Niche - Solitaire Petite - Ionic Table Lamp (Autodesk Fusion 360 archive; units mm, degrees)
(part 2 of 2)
sketch "Sketch4" plane through (0, 23.8125, 0) normal (0, 1, 0) x axis (-1, 0, 0)
  line L1 (-7.1437, -2.6987) -> (-7.1437, 2.6987)
  line L2 (5.8737, -3.9688) -> (-5.8737, -3.9688)
  line L3 (7.1437, 2.6987) -> (7.1437, -2.6987)
  line L4 (-5.8737, 3.9688) -> (5.8737, 3.9688)
  line L5 (-3.81, 6.604) -> (3.81, 6.604)
  line L6 (3.81, -6.604) -> (-3.81, -6.604)
  line L7 (-10.414, 0) -> (10.414, 0)
  arc A1 centre (-5.8737, 2.6987) radius 1.27 clockwise from (-7.1437, 2.6987) to (-5.8737, 3.9688)
  arc A2 centre (-5.8737, -2.6987) radius 1.27 clockwise from (-5.8737, -3.9688) to (-7.1437, -2.6987)
  arc A3 centre (5.8737, -2.6987) radius 1.27 clockwise from (7.1437, -2.6987) to (5.8737, -3.9688)
  arc A4 centre (5.8737, 2.6987) radius 1.27 clockwise from (5.8737, 3.9688) to (7.1437, 2.6987)
  arc A5 centre (-3.81, 0) radius 6.604 clockwise from (-3.81, -6.604) to (-3.81, 6.604)
  arc A6 centre (3.81, 0) radius 6.604 clockwise from (3.81, 6.604) to (3.81, -6.604)
  point P20 (10.414, 0)
  point P21 (-10.414, 0)
  tangent L5 A5
  tangent A5 L6
  parallel L5 L6
  tangent L6 A6
  tangent L5 A6
  midpoint A6 P20
  midpoint A5 P21
  perpendicular L1 L7
extrude "Extrude4" add sketch "Sketch4" profile of A1 L1 A2 L2 A3 L3 A4 L4 L5 A5 L6 A6 against normal blind 2.286
chamfer "Chamfer2" distance 1.778
fillet "Fillet3" radius 1.778
fillet "Fillet4" radius 0.254
fillet "Fillet5" radius 0.254
fillet "Fillet6" radius 0.254
fillet "Fillet7" radius 3.175
sketch "Sketch5" plane through (0, 0, 0) normal (0, -1, 0) x axis (1, 0, 0)
  line L1 (-13.2397, -5.715) -> (-13.2397, 5.715)
  line L2 (9.6837, -9.271) -> (-9.6837, -9.271)
  line L3 (13.2397, 5.715) -> (13.2397, -5.715)
  line L4 (-9.6837, 9.271) -> (9.6837, 9.271)
  line L5 (-6.35, -3.175) -> (-6.35, 3.175)
  line L6 (6.35, 3.175) -> (-6.35, -3.175)
  line L7 (-6.35, 3.175) -> (6.35, -3.175)
  line L8 (-4.7625, 3.175) -> (-6.35, 3.175)
  line L9 (-4.7625, -3.175) -> (-4.7625, 3.175)
  line L10 (-6.35, -3.175) -> (-4.7625, -3.175)
  line L11 (-6.35, 3.175) -> (-6.35, -3.175)
  line L12 (0, -3.302) -> (0, 3.81)
  line L13 (4.7625, -3.175) -> (4.7625, 3.175)
  line L14 (4.7625, 3.175) -> (6.35, 3.175)
  line L15 (6.35, -3.175) -> (6.35, 3.175)
  line L16 (6.35, -3.175) -> (4.7625, -3.175)
  arc A1 centre (-9.6837, 5.715) radius 3.556 clockwise from (-13.2397, 5.715) to (-9.6837, 9.271)
  arc A2 centre (-9.6837, -5.715) radius 3.556 clockwise from (-9.6837, -9.271) to (-13.2397, -5.715)
  arc A3 centre (9.6837, -5.715) radius 3.556 clockwise from (13.2397, -5.715) to (9.6837, -9.271)
  arc A4 centre (9.6837, 5.715) radius 3.556 clockwise from (9.6837, 9.271) to (13.2397, 5.715)
  point P18 (0, 0)
  point P1 (0, 0)
  point P14 (-6.35, -3.175)
  point P27 (6.35, -3.175)
  point P17 (-6.35, 3.175)
  point P26 (6.35, 3.175)
  point P19 (-4.7625, 3.175)
  point P24 (4.7625, 3.175)
  point P20 (-4.7625, -3.175)
  point P25 (4.7625, -3.175)
  point P21 (-6.35, -3.175)
  point P28 (6.35, -3.175)
  point P15 (6.35, -3.175)
  point P16 (6.35, 3.175)
  coincident L6 P18
  coincident L7 P18
  coincident P1 P18
  horizontal L8
  vertical L9
  horizontal L10
  vertical L11
  vertical L12
  symmetric P14 L12 P27
  symmetric P17 L12 P26
  symmetric P19 L12 P24
  symmetric P20 L12 P25
  symmetric P21 L12 P28
  dimension "d36" distance P15 P16 = 6.35
  dimension "d37" distance P17 P19 = 1.5875
extrude "Extrude5" add sketch "Sketch5" profile of L5 L8 L9 L10 L11 L13 L14 L15 L16 along normal blind 15.875
sketch "Sketch7" plane through (0, 0, 3.175) normal (0, 0, 1) x axis (-1, 0, 0)
  line L1 (-4.7625, 0) -> (-6.35, 0)
  line L2 (-4.7625, 15.875) -> (-4.7625, 0)
  line L3 (-6.35, 15.875) -> (-4.7625, 15.875)
  line L4 (-6.35, 0) -> (-6.35, 15.875)
  line L5 (-4.7625, 15.875) -> (-6.35, 15.875)
  line L6 (-4.7625, 9.525) -> (-4.7625, 15.875)
  line L7 (-6.35, 9.525) -> (-4.7625, 9.525)
  line L8 (-6.35, 15.875) -> (-6.35, 9.525)
  point P5 (-6.35, 15.875)
  point P6 (-6.35, 15.875)
  point P9 (-6.35, 9.525)
  horizontal L5
  vertical L6
  horizontal L7
  vertical L8
  coincident P5 P6
  dimension "d45" distance P6 P9 = 6.35
extrude "Extrude7" add sketch "Sketch7" profile of L2 L3 L4 L5 L6 L7 L8 against normal blind 7.9375 and along normal blind 1.5875
chamfer "Chamfer3" distance 0.508
chamfer "Chamfer4" distance 0.635 distance 0.635
sketch "Sketch6" plane through (6.35, 0, 0) normal (1, 0, 0) x axis (0, 1, 0)
  line L1 (0, -3.175) -> (-9.525, -3.175)
  line L2 (0, 3.175) -> (0, -3.175)
  line L3 (-9.525, 3.175) -> (0, 3.175)
  line L4 (-15.367, -4.6355) -> (-15.367, 4.6355)
  line L5 (-11.43, 0) -> (-16.002, 0)
  line L6 (-9.525, -4.7625) -> (-15.24, -4.7625)
  line L7 (-9.525, -3.175) -> (-9.525, -4.7625)
  line L8 (-9.525, 4.7625) -> (-9.525, 3.175)
  line L9 (-15.24, 4.7625) -> (-9.525, 4.7625)
  line L10 (-15.24, -4.7625) -> (-15.367, -4.6355)
  line L11 (-15.367, 4.6355) -> (-15.24, 4.7625)
  circle C1 centre (-11.43, 0) radius 1.5875
  point P9 (-11.43, 0)
  point P10 (-11.43, 0)
  perpendicular L4 L5
  coincident P9 P10
  dimension "d42" diameter C1 = 3.175
extrude "Extrude6" cut sketch "Sketch6" profile of C1 against normal blind 20.32
chamfer "Chamfer5" distance 3.175 distance 1.5875 distance 3.175 distance 1.5875
component_from_bodies "Body->Comp"
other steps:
base_feature "Base Feature" bodies "2-Pole Plug End"
create_component "CreateComponent1"
remove_body "RemoveBody1"
named bodies: "2-Pole Plug End"

design "Marble Base - Plastic Insert"
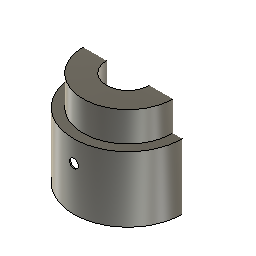
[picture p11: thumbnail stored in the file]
sketch "Sketch1" plane through (0, 0, 0) normal (0, 0, 1) x axis (1, 0, 0)
  circle C1 centre (0, 0) radius 50.038
  point P1 (0, 0)
  point P2 (0, 0)
  coincident P1 P2
  dimension "d1" diameter C1 = 100.076
extrude "Extrude1" new body sketch "Sketch1" along normal blind 72.898 bodies "Plastic Insert"
shell "Shell1" innerThickness 1.016
work_plane "WorkPlane1" AlongDistance 18.034
sketch "Sketch2" plane through (0, 0, 90.932) normal (0, 0, 1) x axis (1, 0, 0)
  circle C1 centre (0, 0) radius 20.701
  point P1 (0, 0)
  point P2 (0, 0)
  coincident P1 P2
  dimension "d6" diameter C1 = 41.402
extrude "Extrude2" add sketch "Sketch2" against normal blind 65.024
shell "Shell2" innerThickness 1.016
sketch "Sketch3" plane through (0, 0, 0) normal (0, 1, 0) x axis (1, 0, 0)
  line L1 (5.08, -20.32) -> (-5.08, -20.32)
  line L2 (5.08, 20.32) -> (5.08, -20.32)
  line L3 (-5.08, 20.32) -> (5.08, 20.32)
  line L4 (-5.08, -20.32) -> (-5.08, 20.32)
  line L5 (5.08, 20.32) -> (-5.08, -20.32)
  line L6 (-5.08, 20.32) -> (5.08, -20.32)
  point P6 (0, 0)
  point P1 (0, 0)
  horizontal L1
  perpendicular L1 L2
  parallel L1 L3
  parallel L2 L4
  coincident L5 P6
  coincident L6 P6
  coincident P1 P6
extrude "Extrude3" cut sketch "Sketch3" profile of L1 L2 L3 L4 along normal blind 91.44
sketch "Sketch4" plane through (0, 0, 0) normal (0, 1, 0) x axis (1, 0, 0)
  line L1 (0, -40.64) -> (0, 0)
  circle C1 centre (0, -40.64) radius 4.064
  point P1 (0, 0)
  point P2 (0, 0)
  point P3 (0, -40.64)
  point P4 (0, -40.64)
  coincident P1 P2
  vertical L1
  coincident P3 P4
  dimension "d12" diameter C1 = 8.128
work_plane "WorkPlane2" AlongDistance -91.44
sketch "Sketch5" plane through (0, -91.44, 0) normal (0, 1, 0) x axis (1, 0, 0)
  circle C1 centre (0, -40.64) radius 4.064
extrude "Extrude4" cut sketch "Sketch5" along normal blind 63.5
sketch "Sketch6" plane through (0, 0, 26.924) normal (0, 0, 1) x axis (-1, 0, 0)
  circle C1 centre (0, 0) radius 19.685
  circle C2 centre (0, 0) radius 5.461
  concentric C1 C2
  dimension "d16" diameter C2 = 10.922
extrude "Extrude5" cut sketch "Sketch6" profile of C2 against normal blind 15.24
sketch "Sketch7" plane through (0, 0, 72.898) normal (0, 0, 1) x axis (-1, 0, 0)
  circle C1 centre (0, 0) radius 20.701
  circle C2 centre (0, 0) radius 50.038
  circle C3 centre (0, 0) radius 20.701
  circle C4 centre (0, 0) radius 45.72
  point P1 (0, 0)
  point P3 (0, 0)
  point P4 (0, 0)
  coincident P1 P3
  coincident P1 P4
extrude "Extrude6" add sketch "Sketch7" profile of C1 C3 C4 along normal blind 18.034
sketch "Sketch8" plane through (0, 0, 71.882) normal (0, 0, -1) x axis (1, 0, 0)
  circle C1 centre (0, 0) radius 20.701
  circle C2 centre (0, 0) radius 49.022
  circle C3 centre (0, 0) radius 20.701
  circle C4 centre (0, 0) radius 44.704
  point P1 (0, 0)
  point P3 (0, 0)
  point P4 (0, 0)
  coincident P1 P3
  coincident P1 P4
  dimension "d21" diameter C4 = 89.408
extrude "Extrude7" cut sketch "Sketch8" profile of C1 C3 C4 against normal blind 17.78
extrude "Extrude8" add of existing geometry blind 9.398
extrude "Extrude9" cut of existing geometry blind -9.398
component_from_bodies "Body->Comp"
offset_faces "OffsetFaces1" distance 4.445
offset_faces "OffsetFaces2" distance -4.445
offset_faces "OffsetFaces3" distance 3.175
offset_faces "OffsetFaces4" distance 3.175
offset_faces "OffsetFaces5" distance 3.175
offset_faces "OffsetFaces6" distance -3.175
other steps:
base_feature "Base Feature" bodies "Plastic Insert"
create_component "CreateComponent1"
remove_body "RemoveBody1"
named bodies: "Plastic Insert"

design "Rubber Grommet"
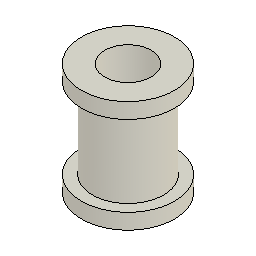
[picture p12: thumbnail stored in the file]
sketch "Sketch1" plane through (0, 0, 0) normal (0, 1, 0) x axis (1, 0, 0)
  line L1 (0, 3.048) -> (0, -12.7)
  line L2 (5.842, 0.508) -> (5.842, -12.7)
  line L3 (3.81, 3.048) -> (3.81, -15.24)
  line L4 (7.62, -12.7) -> (7.62, -15.24)
  line L5 (7.62, 3.048) -> (7.62, 0.508)
  line L6 (7.62, 0.508) -> (5.842, 0.508)
  line L7 (7.62, -12.7) -> (5.842, -12.7)
  line L8 (7.62, -15.24) -> (3.81, -15.24)
  line L9 (7.62, 3.048) -> (3.81, 3.048)
  vertical L1
  collinear L4 L5
revolve "Revolve1" sketch "Sketch1" AlongAngle 360 bodies "Rubber Grommet"
component_from_bodies "Body->Comp"
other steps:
base_feature "Base Feature" bodies "Rubber Grommet"
create_component "CreateComponent1"
remove_body "RemoveBody1"
named bodies: "Rubber Grommet"

design "Trove - TL"
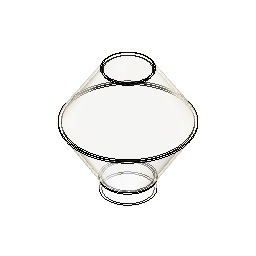
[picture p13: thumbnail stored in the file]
derived_base_feature "Derived Base Feature" bodies "Trove"
hole "Hole1" HoleDepth 88.9 HoleDiameter 44.45 TipAngle 118
sketch "Sketch1" plane through (0, 0, 0) normal (1, 0, 0) x axis (0, 1, 0)
  line L1 (0, 243.0601) -> (0, 247.8226)
  line L2 (-50.8, -12.7122) -> (-50.8, 10.9447)
  line L3 (0, -25.4) -> (0, 243.0601)
  line L4 (-46.0375, -12.7122) -> (-50.8, -12.7122)
  line L5 (-46.0375, -12.7122) -> (-46.0375, 12.3043)
  line L6 (-45.9716, 247.8226) -> (0, 247.8226)
  line L7 (-43.3841, 243.0601) -> (0, 243.0601)
  line L8 (-122.8321, 128.6352) -> (-51.757, 14.2971)
  line L9 (-117.1907, 128.5808) -> (-46.9945, 15.6567)
  line L10 (-48.6353, 246.3754) -> (-122.7993, 132.0392)
  line L11 (-46.0478, 241.6129) -> (-117.1579, 131.9848)
  arc A1 centre (-57.15, 10.9447) radius 6.35 clockwise from (-51.757, 14.2971) to (-50.8, 10.9447)
  arc A2 centre (-52.3875, 12.3043) radius 6.35 clockwise from (-46.9945, 15.6567) to (-46.0375, 12.3043)
  arc A3 centre (-114.4942, 130.257) radius 3.175 between (-117.1579, 131.9848) and (-117.1907, 128.5808)
  arc A4 centre (-120.1356, 130.3114) radius 3.175 between (-122.7993, 132.0392) and (-122.8321, 128.6352)
  arc A5 centre (-45.9716, 244.6476) radius 3.175 between (-45.9716, 247.8226) and (-48.6353, 246.3754)
  arc A6 centre (-43.3841, 239.8851) radius 3.175 clockwise from (-46.0478, 241.6129) to (-43.3841, 243.0601)
  point P3 (0, 247.8226)
  point P4 (0, 243.0601)
  vertical L1
  vertical L3
  tangent L5 A2
  perpendicular L1 L6
  perpendicular L1 L7
  tangent L11 A3
  tangent L9 A3
  tangent L10 A4
  tangent L8 A4
  equal A3 A4
  tangent L6 A5
  tangent L10 A5
  tangent L11 A6
  tangent L7 A6
  dimension "d8" distance P3 P4 = 4.7625
  dimension "d11" radius A2 = 6.35
  dimension "d15" radius A3 = 3.175
  dimension "d16" radius A5 = 3.175
  dimension "d17" radius A6 = 3.175
revolve "Revolve1" sketch "Sketch1" AlongAngle 180 bodies "Trove - TL"
revolve "Revolve2" sketch "Sketch1" AlongAngle -180
component_from_bodies "Body->Comp"
remove_body "RemoveBody2"
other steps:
base_feature "Base Feature" bodies "Trove - TL"
create_component "CreateComponent1"
remove_body "RemoveBody1"
named bodies: "Trove", "Trove - TL"

design "T9-5In"
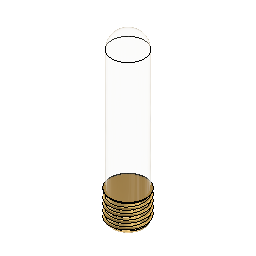
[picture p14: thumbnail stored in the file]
sketch "Sketch1" plane through (0, 0, 0) normal (0, 1, 0) x axis (1, 0, 0)
  line L1 (0, 0) -> (0, -127)
  line L2 (12.7, -127) -> (-12.7, -127)
  line L3 (12.7, -12.7) -> (12.7, -127)
  line L4 (-12.7, -127) -> (-12.7, -12.7)
  arc A1 centre (0, -12.7) radius 12.7 clockwise from (-12.7, -12.7) to (12.7, -12.7)
  point P1 (0, 0)
  point P3 (0, 0)
  coincident P1 P3
  vertical L1
  horizontal L2
  vertical L3
  vertical L4
revolve "Revolve1" sketch "Sketch1" AlongAngle 360 bodies "BU-T10-5-LED-120V"
derived_base_feature "Derived Base Feature" bodies "E26 Base"
move "Move1"
component_from_bodies "Body->Comp"
copy_paste "CutPaste"
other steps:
base_feature "Base Feature" bodies "BU-T10-5-LED-120V"
create_component "CreateComponent1"
create_component "CreateComponent2"
remove_body "RemoveBody1"
remove_instance "RemoveInstance1"
named bodies: "BU-T10-5-LED-120V", "E26 Base"

design "Orb 8.5In - Solitaire Petite"
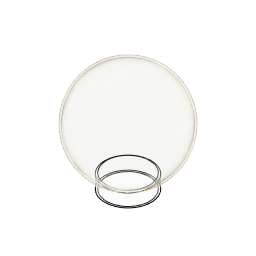
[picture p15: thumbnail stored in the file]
sketch "Sketch1" plane through (0, 0, 0) normal (0, 1, 0) x axis (1, 0, 0)
  line L1 (0, 190.5) -> (0, -127)
  line L2 (50.8, 190.5) -> (50.8, -127)
  line L3 (-50.8, 190.5) -> (-50.8, -127)
  line L4 (50.8, 95.25) -> (-50.8, 95.25)
  line L5 (50.8, 123.825) -> (-50.8, 123.825)
  line L6 (101.6, -107.95) -> (0, -107.95)
  circle C1 centre (0, 0) radius 107.95
  point P1 (0, 0)
  point P2 (0, 0)
  point P5 (50.8, -127)
  point P7 (-50.8, -127)
  point P6 (50.8, 190.5)
  point P8 (-50.8, 190.5)
  point P9 (-50.8, 95.25)
  point P10 (50.8, 95.25)
  point P13 (0, -107.95)
  coincident P1 P2
  vertical L1
  symmetric L1 P5 P7
  symmetric L1 P6 P8
  coincident C1 P9
  coincident L3 P9
  coincident C1 P10
  coincident L2 P10
  perpendicular L2 L4
  coincident C1 P13
  coincident L1 P13
  tangent C1 L6
  dimension "d1" diameter C1 = 215.9
  dimension "d2" = 50.8
  dimension "d4" = -28.575
revolve "Revolve1" sketch "Sketch1" AlongAngle 360 bodies "Orb-8.5"
shell "Shell1" innerThickness 3.81
component_from_bodies "Body->Comp"
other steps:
base_feature "Base Feature" bodies "Orb-8.5"
create_component "CreateComponent1"
remove_body "RemoveBody1"
named bodies: "Orb-8.5"

design "Dart"
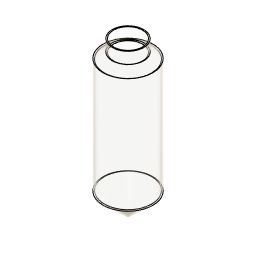
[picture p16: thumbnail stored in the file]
sketch "Sketch1" plane through (0, 0, 0) normal (0, 0, 1) x axis (1, 0, 0)
work_plane "WorkPlane1" AlongDistance 76.2
sketch "Sketch2" plane through (0, 0, 76.2) normal (0, 0, 1) x axis (1, 0, 0)
sketch "Sketch3" plane through (0, 0, 76.2) normal (0, 0, 1) x axis (1, 0, 0)
sketch "Sketch4" plane through (0, 0, 76.2) normal (0, 0, 1) x axis (1, 0, 0)
  circle C1 centre (0, 0) radius 82.55
  point P1 (0, 0)
  point P2 (0, 0)
  coincident P1 P2
  dimension "d2" diameter C1 = 165.1
loft "Loft1" sketch "Sketch4" bodies "Dart Grand"
extrude "Extrude1" add of existing geometry blind 381
work_plane "WorkPlane2" AlongDistance 19.05
sketch "Sketch5" plane through (0, 0, 476.25) normal (0, 0, 1) x axis (1, 0, 0)
  circle C1 centre (0, 0) radius 52.07
  point P1 (0, 0)
  point P2 (0, 0)
  coincident P1 P2
  dimension "d6" diameter C1 = 104.14
loft "Loft2" sketch "Sketch5"
extrude "Extrude2" add of existing geometry blind 38.1
shell "Shell3" innerThickness 3.81
component_from_bodies "Body->Comp"
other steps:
base_feature "Base Feature" bodies "Dart Grand"
create_component "CreateComponent1"
remove_body "RemoveBody1"
named bodies: "Dart Grand"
